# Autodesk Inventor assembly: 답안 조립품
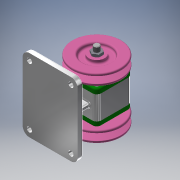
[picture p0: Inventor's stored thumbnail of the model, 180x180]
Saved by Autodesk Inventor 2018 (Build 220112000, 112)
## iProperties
Created: 2020-11
Part Number: 답안 조립품
Document SubType Name: Assembly
Designer: Administrator
Author: Administrator
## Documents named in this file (10)
- C:\Users\Administrator\Desktop\701106V1049\답안 조립품.iam
- C:\Users\Administrator\Desktop\701106V1049\본체.ipt
- C:\Users\Administrator\Desktop\701106V1049\축.ipt
- C:\Users\Administrator\Desktop\701106V1049\베어링 6004.ipt
- C:\Users\Administrator\Desktop\701106V1049\커버.ipt
- C:\Users\Administrator\Desktop\701106V1049\오일 실 17 30 5.ipt
- C:\Users\Administrator\Desktop\701106V1049\볼트 M4.ipt
- C:\Users\Administrator\Desktop\701106V1049\키 5 x 5 x 12.ipt
- C:\Users\Administrator\Desktop\701106V1049\V-벨트풀리.ipt
- C:\Users\Administrator\Desktop\701106V1049\너트 M10x1.ipt
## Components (2 placed, 1 different names)
1. V-벨트풀리:1
2. V-벨트풀리:2
